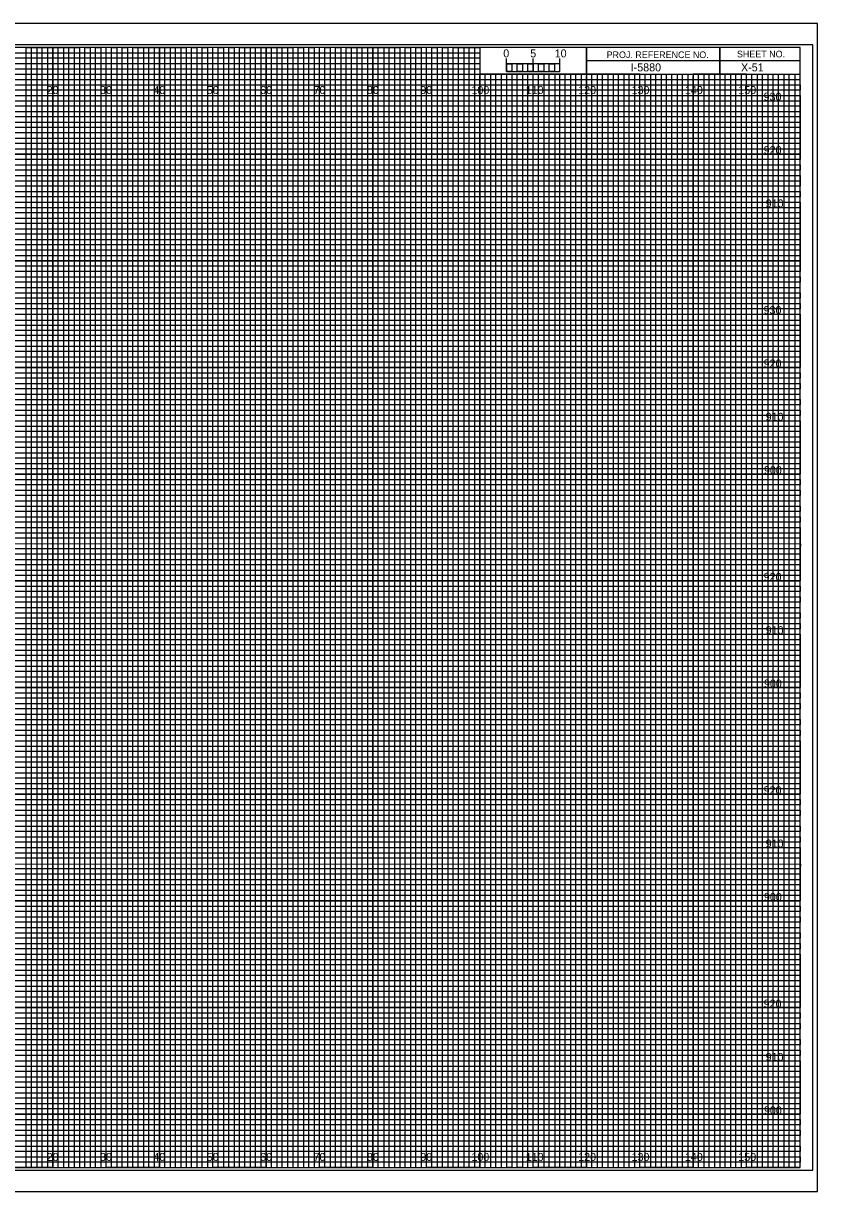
# Model space of a CAD drawing. Extents: x -13 to 323, y 876 to 1094.
# Drawn here: x 174.5 to 323.3, y 875.5 to 1094.5 of the extents above; entities that cross this region are included whole.
import ezdxf

# ---------------------------------------------------------------- set-up
doc = ezdxf.new("R2010")
doc.units = 0
for name, color, linetype in [('Prop XS Bar Scale Labels', 7, 'Continuous'), ('Prop XS Elevation Labels', 7, 'Continuous'), ('Prop XS Offset Labels', 7, 'Continuous'), ('Prop XS Project Number', 7, 'Continuous'), ('Prop XS Sheet Number', 7, 'Continuous'), ('Sheet Cross Section CELL', 7, 'Continuous'), ('Sheet Cross Section Grid Major CELL', 7, 'Continuous'), ('Sheet Cross Section Grid Middle CELL', 7, 'Continuous'), ('Sheet Cross Section Grid Minor 1 CELL', 7, 'Continuous'), ('Sheet Cross Section Grid Minor 2 CELL', 7, 'Continuous'), ('Sheet Cross Section Scale CELL', 7, 'Continuous'), ('Sheet Cutting Line CELL', 7, 'Continuous'), ('Sheet DOT Grid CELL', 7, 'Continuous'), ('Sheet Plot Border Inside CELL', 7, 'Continuous'), ('Sheet Plot Border Outside CELL', 7, 'Continuous')]:
    doc.layers.add(name, color=color, linetype=linetype)

msp = doc.modelspace()

# ---------------------------------------------------------------- linework, layer by layer
at = {"layer": 'Sheet Cross Section CELL'}
for p, q in [((305, 1090), (305, 1085)), ((305, 1085), (305, 1090)), ((280, 1087.5), (280, 1085)), ((320, 1087.49), (280, 1087.49)), ((280, 1085), (320, 1085))]:
    msp.add_line(p, q, dxfattribs=at)
for points in [[(320, 1090), (0, 1090), (0, 880), (320, 880)], [(280, 1090), (260, 1090), (260, 1085.03), (280, 1085.03)], [(320, 1090), (280, 1090), (280, 1085), (320, 1085)]]:
    msp.add_lwpolyline(points, close=True, dxfattribs=at)
at = {"layer": 'Sheet Cross Section Grid Major CELL'}
for p, q in [((190, 1090), (180, 1090)), ((180, 1090), (180, 880)), ((190, 880), (190, 1090)), ((210, 1090), (200, 1090)), ((200, 1090), (200, 880)), ((210, 880), (210, 1090)), ((230, 1090), (220, 1090)), ((220, 1090), (220, 880)), ((230, 880), (230, 1090)), ((250, 1090), (240, 1090)), ((240, 1090), (240, 880)), ((250, 880), (250, 1090)), ((260, 1090), (260, 880)), ((270, 880), (270, 1085)), ((290, 1085), (280, 1085)), ((280, 1085), (280, 880)), ((290, 880), (290, 1085)), ((310, 1085), (300, 1085)), ((300, 1085), (300, 880)), ((310, 880), (310, 1085)), ((180, 880), (170, 880)), ((200, 880), (190, 880)), ((220, 880), (210, 880)), ((240, 880), (230, 880)), ((260, 880), (250, 880)), ((280, 880), (270, 880)), ((300, 880), (290, 880)), ((320, 880), (310, 880)), ((320, 880), (320, 880))]:
    msp.add_line(p, q, dxfattribs=at)
for points in [[(0, 1080), (320, 1080), (320, 1070), (0, 1070)], [(0, 1060), (320, 1060), (320, 1050), (0, 1050)], [(0, 1040), (320, 1040), (320, 1030), (0, 1030)], [(0, 1020), (320, 1020), (320, 1010), (0, 1010)], [(0, 1000), (320, 1000), (320, 990), (0, 990)], [(0, 980), (320, 980), (320, 970), (0, 970)], [(0, 960), (320, 960), (320, 950), (0, 950)], [(0, 940), (320, 940), (320, 930), (0, 930)], [(0, 920), (320, 920), (320, 910), (0, 910)], [(0, 900), (320, 900), (320, 890), (0, 890)]]:
    msp.add_lwpolyline(points, dxfattribs=at)
at = {"layer": 'Sheet Cross Section Grid Middle CELL'}
for points in [[(165, 880), (175, 880), (175, 1090), (185, 1090), (185, 880), (195, 880), (195, 1090), (205, 1090), (205, 880), (215, 880), (215, 1090), (225, 1090), (225, 880), (235, 880), (235, 1090), (245, 1090), (245, 880), (255, 880), (255, 1090), (259.93, 1090), (260, 1090), (260, 1085), (264.99, 1085), (264.99, 880), (275, 880), (275, 1085), (285, 1085), (285, 880), (295, 880), (295, 1085), (305, 1085), (305, 880), (315, 880), (315, 1085)], [(0, 1085), (275, 1085)], [(0, 1065), (320, 1065), (320, 1075), (0, 1075)], [(0, 1045), (320, 1045), (320, 1055), (0, 1055)], [(0, 1025), (320, 1025), (320, 1035), (0, 1035)], [(0, 1005), (320, 1005), (320, 1015), (0, 1015)], [(0, 985), (320, 985), (320, 995), (0, 995)], [(0, 965), (320, 965), (320, 975), (0, 975)], [(0, 945), (320, 945), (320, 955), (0, 955)], [(0, 925), (320, 925), (320, 935), (0, 935)], [(0, 905), (320, 905), (320, 915), (0, 915)], [(0, 885), (320, 885), (320, 895), (0, 895)]]:
    msp.add_lwpolyline(points, dxfattribs=at)
at = {"layer": 'Sheet Cross Section Grid Minor 1 CELL'}
for p, q in [((0, 1089), (260, 1089)), ((260, 1089), (260, 1087.98)), ((260, 1087.98), (0, 1087.98)), ((0, 1087), (260, 1087)), ((260, 1087), (260, 1085.89)), ((260, 1085.89), (0, 1085.89)), ((0, 1084), (320, 1084))]:
    msp.add_line(p, q, dxfattribs=at)
for points in [[(0, 1083), (270, 1083), (320, 1083), (320, 1082), (0, 1082)], [(0, 1081), (320, 1081), (320, 1079), (0, 1079)], [(0, 1078), (320, 1078), (320, 1077), (0, 1076.98)], [(0, 1076), (320, 1076), (320, 1074), (0, 1074)], [(0, 1073), (320, 1073), (320, 1072), (0, 1072)], [(0, 1071), (320, 1071), (320, 1069), (0, 1069)], [(0, 1068), (320, 1068), (320, 1067), (0, 1067)], [(0, 1066), (320, 1066), (320, 1064), (0, 1064)], [(0, 1063), (320, 1063), (320, 1062), (0, 1062)], [(0, 1061), (320, 1061), (320, 1059), (0, 1059)], [(0, 1058), (320, 1058), (320, 1057), (0, 1057)], [(0, 1056), (320, 1056), (320, 1053.95), (320, 1053), (320, 1052), (0, 1052)], [(0, 1054), (320, 1054), (320, 1053), (0, 1053)], [(0, 1051), (320, 1051), (320, 1049), (0, 1049.03)], [(0, 1049.03), (320, 1049), (320, 1048), (0, 1048)], [(0, 1047), (320, 1047), (320, 1046), (0, 1046)], [(0, 1044), (320, 1044), (320, 1043), (0, 1043)], [(0, 1042), (320, 1042), (320, 1041), (0, 1041)], [(-0.07, 1038.89), (320, 1038.89), (320, 1037.88), (-0.07, 1037.88)], [(0, 1037), (320, 1037), (320, 1036), (0, 1036)], [(0, 1034), (320, 1034), (320, 1033), (0, 1033)], [(0, 1032), (320, 1032), (320, 1031), (0, 1031)], [(0, 1029), (320, 1029), (320, 1028), (0, 1028)], [(0, 1027), (320, 1027), (320, 1026), (0, 1026)], [(0, 1024), (320, 1024), (320, 1023), (0, 1023)], [(0, 1022), (320, 1022), (320, 1021), (0, 1021)], [(0, 1019), (320, 1019), (319.99, 1017.98), (0, 1018)], [(0, 1017), (320, 1017), (320, 1016), (0, 1016)], [(0, 1014), (320, 1014), (320, 1013), (0, 1013)], [(0, 1012), (320, 1012), (320, 1011), (0, 1011)], [(0, 1009), (320, 1009), (320, 1008), (0, 1008)], [(0, 1007), (320, 1007), (320, 1006), (0, 1006)], [(0, 1004), (320, 1004), (320, 1003), (0, 1003)], [(0, 1002), (320, 1002), (320, 1001), (0, 1001)], [(0, 999), (320, 999), (320, 998), (0, 998)], [(0, 996.99), (320.07, 996.91), (320, 996), (0, 996)], [(0, 994), (320, 994), (320, 993), (0, 993)], [(0, 992), (320, 992), (320, 991), (0, 991)], [(0, 989), (320, 989), (320, 988), (0, 988)], [(0, 987), (320, 987), (320, 986), (0, 986)], [(0, 984), (320, 984), (320, 983), (0, 983)], [(0, 982), (320, 982), (320, 981), (0, 981)], [(0, 979), (320, 979), (320, 978), (0, 978)], [(0, 977), (320, 977), (320, 976), (0, 976)], [(0, 974), (320, 974), (320, 973), (0, 973)], [(0, 972), (320, 972), (320, 971), (0, 971)], [(0, 969), (320, 969), (320, 968), (0, 968)], [(0, 967), (320, 967), (320, 966), (0, 966)], [(0, 964), (320, 964), (320, 963), (0, 963)], [(0, 962), (320, 962), (320, 961), (0, 961)], [(0, 959), (320, 959), (319.99, 957.98), (0, 958)], [(0, 957), (320, 957), (320, 956), (0, 956)], [(0, 954), (320, 954), (320, 953), (0, 953)], [(0, 952), (320, 952), (320, 951), (0, 951)], [(0, 949), (320, 949), (320, 948), (0, 948)], [(0, 947), (320, 947), (320, 946), (0, 946)], [(0, 944), (320, 944), (320, 943), (0, 943)], [(0, 942), (320, 942), (320, 941), (0, 941)], [(0, 939), (320, 939), (320, 938), (0, 938)], [(0, 936.99), (320.07, 936.91), (320, 936), (0, 936)], [(0, 934), (320, 934), (320, 933), (0, 933)], [(0, 932), (320, 932), (320, 931), (0, 931)], [(0, 929), (320, 929), (320, 928), (0, 928)], [(0, 927), (320, 927), (320, 926), (0, 926)], [(0, 924), (320, 924), (320, 923), (0, 923)], [(0, 922), (320, 922), (320, 921), (0, 921)], [(0, 919), (320, 919), (320, 918), (0, 918)], [(0, 917), (320, 917), (320, 916), (0, 916)], [(0, 914), (320, 914), (320, 913), (0, 913)], [(0, 912), (320, 912), (320, 911), (0, 911)], [(0, 909), (320, 909), (320, 908), (0, 908)], [(0, 907), (320, 907), (320, 906), (0, 906)], [(0, 904), (320, 904), (320, 903), (0, 903)], [(0, 902), (320, 902), (320, 901), (0, 901)], [(0, 899), (320, 899), (320, 898), (0, 898)], [(0, 897), (320, 897), (320, 896), (0, 896)], [(0, 894), (320, 894), (320, 893), (0, 893)], [(0, 892), (320, 892), (320, 891), (0, 891)], [(0, 889), (320, 889), (320, 888), (0, 888)], [(0, 887), (320, 887), (320, 886), (0, 886)], [(0, 884), (320, 884), (320, 883), (0, 883)], [(0, 882), (320, 882), (320, 881), (0, 881)]]:
    msp.add_lwpolyline(points, dxfattribs=at)
at = {"layer": 'Sheet Cross Section Grid Minor 2 CELL'}
for p, q in [((267, 1085), (266.01, 1085)), ((266.01, 1085), (266.01, 880)), ((267, 880), (267, 1085)), ((269, 1085), (268, 1085)), ((268, 1085), (268, 880)), ((269, 880), (269, 1085)), ((266.01, 880), (265, 880)), ((268, 880), (267, 880))]:
    msp.add_line(p, q, dxfattribs=at)
for points in [[(175, 880), (176, 880), (176, 1090), (177, 1090), (177, 880)], [(177, 880), (178, 880), (178, 1090), (179, 1090), (179, 880)], [(180, 880), (181, 880), (181, 1090), (182, 1090), (182, 880)], [(182, 880), (183, 880), (183, 1090), (184, 1090), (184, 880)], [(185, 880), (186, 880), (186, 1090), (187, 1090), (187, 880)], [(187, 880), (188, 880), (188, 1090), (189, 1090), (189, 880)], [(190, 880), (191, 880), (191, 1090), (192, 1090), (192, 880)], [(192, 880), (193, 880), (193, 1090), (194, 1090), (194, 880)], [(195, 880), (196, 880), (196, 1090), (197, 1090), (197, 880)], [(197, 880), (198, 880), (198, 1090), (199, 1090), (199, 880)], [(200, 880), (201, 880), (201, 1090), (202, 1090), (202, 880)], [(202, 880), (203, 880), (203, 1090), (204, 1090), (204, 880)], [(205, 880), (206, 880), (206, 1090), (207, 1090), (207, 880)], [(207, 880), (208, 880), (208, 1090), (209, 1090), (209, 880)], [(210, 880), (211, 880), (211, 1090), (212, 1090), (212, 880)], [(212, 880), (213, 880), (213, 1090), (214, 1090), (214, 880)], [(215, 880), (216, 880), (216, 1090), (217, 1090), (217, 880)], [(217, 880), (218, 880), (218, 1090), (219, 1090), (219, 880)], [(220, 880), (221, 880), (221, 1090), (222, 1090), (222, 880)], [(222, 880), (223, 880), (223, 1090), (224, 1090), (224, 880)], [(225, 880), (226, 880), (226, 1090), (227, 1090), (227, 880)], [(227, 880), (228, 880), (228, 1090), (229, 1090), (229, 880)], [(230, 880), (231, 880), (231, 1090), (232, 1090), (232, 880)], [(232, 880), (233, 880), (233, 1090), (234, 1090), (234, 880)], [(235, 880), (236, 880), (236, 1090), (237, 1090), (237, 880)], [(237, 880), (238, 880), (238, 1090), (239, 1090), (239, 880)], [(240, 880), (241, 880), (241, 1090), (242, 1090), (242, 880)], [(242, 880), (243, 880), (243, 1090), (244, 1090), (244, 880)], [(245, 880), (246, 880), (246, 1090), (247, 1090), (247, 880)], [(247, 880), (248, 880), (248, 1090), (249, 1090), (249, 880)], [(250, 880), (251, 880), (251, 1090), (252, 1090), (252, 880)], [(252, 880), (253, 880), (253, 1090), (254, 1090), (254, 880)], [(255, 880), (256, 880), (256, 1090), (257, 1090), (257, 880)], [(257, 880), (258, 880), (258, 1090), (259, 1090), (259, 880)], [(260, 880), (261, 880), (261, 1085), (262.02, 1085), (262.02, 880)], [(262, 880), (263, 880), (263, 1085), (263.99, 1085), (263.99, 880)], [(270, 880), (270.98, 880), (270.98, 1085), (272, 1085), (272, 880)], [(272, 880), (273, 880), (273, 1085), (274.05, 1085), (274.05, 880)], [(275, 880), (276, 880), (276, 1085), (277, 1085), (277, 880)], [(277, 880), (278, 880), (278, 1085), (279, 1085), (279, 880)], [(280, 880), (281, 880), (281, 1085), (282, 1085), (282, 880)], [(282, 880), (283, 880), (283, 1085), (284, 1085), (284, 880)], [(285, 880), (286, 880), (286, 1085), (287, 1085), (287, 880)], [(287, 880), (288, 880), (288, 1085), (289, 1085), (289, 880)], [(290, 880), (291, 880), (291, 1085), (292, 1085), (292, 880)], [(292, 880), (293, 880), (293, 1085), (294, 1085), (294, 880)], [(295, 880), (296, 880), (296, 1085), (297, 1085), (297, 880)], [(297, 880), (298, 880), (298, 1085), (299, 1085), (299, 880)], [(300, 880), (301, 880), (301, 1085), (302, 1085), (302, 880)], [(302, 880), (303, 880), (303, 1085), (304, 1085), (304, 880)], [(305, 880), (306, 880), (306, 1085), (307, 1085), (307, 880)], [(307, 880), (308, 880), (308, 1085), (309, 1085), (309, 880)], [(310, 880), (311, 880), (311, 1085), (312, 1085), (312, 880)], [(312, 880), (313, 880), (313, 1085), (314, 1085), (314, 880)], [(315, 880), (316, 880), (316, 1085), (317, 1085), (317, 880)], [(317, 880), (318, 880), (318, 1085), (319, 1085), (319, 880)]]:
    msp.add_lwpolyline(points, dxfattribs=at)
at = {"layer": 'Sheet Cross Section Scale CELL'}
for p, q in [((265, 1085.49), (265, 1087.9)), ((265, 1086.9), (265, 1087.9)), ((270, 1085.49), (270, 1087.9)), ((275, 1085.49), (275, 1087.9)), ((275, 1086.9), (275, 1087.9))]:
    msp.add_line(p, q, dxfattribs=at)
for points in [[(275, 1086.9), (265, 1086.9), (265, 1085.49), (275, 1085.49)], [(265, 1086.9), (266, 1086.9), (266, 1085.49), (265, 1085.49)], [(267, 1086.9), (268, 1086.9), (268, 1085.49), (267, 1085.49)], [(269, 1086.9), (270, 1086.9), (270, 1085.49), (269, 1085.49)], [(271, 1086.9), (272, 1086.9), (272, 1085.49), (271, 1085.49)], [(273, 1086.9), (274, 1086.9), (274, 1085.49), (273, 1085.49)]]:
    msp.add_lwpolyline(points, close=True, dxfattribs=at)
at = {"layer": 'Sheet Cutting Line CELL'}
for p, q in [((323.3, 1094.5), (-13.4, 1094.5)), ((-13.4, 875.5), (323.3, 875.5))]:
    msp.add_line(p, q, dxfattribs=at)
at = {"layer": 'Sheet DOT Grid CELL'}
for p, q in [((180, 880), (180, 1090)), ((190, 880), (190, 1090)), ((200, 880), (200, 1090)), ((210, 880), (210, 1090)), ((220, 880), (220, 1090)), ((230, 880), (230, 1090)), ((240, 880), (240, 1090)), ((250, 880), (250, 1090)), ((260, 880), (260, 1084.69)), ((270, 880), (270, 1084.69)), ((280, 880), (280, 1084.69)), ((290, 880), (290, 1084.69)), ((300, 880), (300, 1084.69)), ((310, 880), (310, 1084.69)), ((0, 1080), (320, 1080)), ((0, 1070), (320, 1070)), ((0, 1060), (320, 1060)), ((0, 1050), (320, 1050)), ((0, 1040), (320, 1040)), ((0, 1030), (320, 1030)), ((0, 1020), (320, 1020)), ((0, 1010), (320, 1010)), ((0, 1000), (320, 1000)), ((0, 990), (320, 990)), ((0, 980), (320, 980)), ((0, 970), (320, 970)), ((0, 960), (320, 960)), ((0, 950), (320, 950)), ((0, 940), (320, 940)), ((0, 930), (320, 930)), ((0, 920), (320, 920)), ((0, 910), (320, 910)), ((0, 900), (320, 900)), ((0, 890), (320, 890))]:
    msp.add_line(p, q, dxfattribs=at)
at = {"layer": 'Sheet Plot Border Inside CELL'}
msp.add_lwpolyline([(-10.8, 879.5), (322.4, 879.5), (322.4, 1090.5), (-10.8, 1090.5)], close=True, dxfattribs=at)
at = {"layer": 'Sheet Plot Border Outside CELL'}
msp.add_lwpolyline([(-13.4, 875.5), (323.3, 875.5), (323.3, 1094.5), (-13.4, 1094.5)], close=True, dxfattribs=at)

# ---------------------------------------------------------------- texts
at = {"layer": 'Prop XS Bar Scale Labels'}
for s, p in [('5', (269.47, 1088.12)), ('10', (274.04, 1088.12))]:
    msp.add_text(s, height=1.5, dxfattribs=at).set_placement(p)
at = {"layer": 'Prop XS Elevation Labels'}
for s, p in [('930', (313.18, 1080)), ('920', (313.19, 1070)), ('910', (313.57, 1060)), ('930', (313.18, 1040)), ('920', (313.19, 1030)), ('910', (313.57, 1020)), ('900', (313.24, 1010)), ('920', (313.19, 990)), ('910', (313.57, 980)), ('900', (313.24, 970)), ('920', (313.19, 950)), ('910', (313.57, 940)), ('900', (313.24, 930)), ('920', (313.19, 910)), ('910', (313.57, 900)), ('900', (313.24, 890))]:
    msp.add_text(s, height=1.5, dxfattribs=at).set_placement(p)
at = {"layer": 'Prop XS Offset Labels'}
for s, p in [('20', (178.86, 1081.25)), ('30', (188.86, 1081.25)), ('40', (198.86, 1081.25)), ('50', (208.86, 1081.25)), ('60', (218.86, 1081.25)), ('70', (228.86, 1081.25)), ('80', (238.86, 1081.25)), ('90', (248.86, 1081.25)), ('100', (258.44, 1081.25)), ('110', (268.62, 1081.25)), ('120', (278.44, 1081.25)), ('130', (288.44, 1081.25)), ('140', (298.44, 1081.25)), ('150', (308.44, 1081.25)), ('20', (178.86, 881.25)), ('30', (188.86, 881.25)), ('40', (198.86, 881.25)), ('50', (208.86, 881.25)), ('60', (218.86, 881.25)), ('70', (228.86, 881.25)), ('80', (238.86, 881.25)), ('90', (248.86, 881.25)), ('100', (258.44, 881.25)), ('110', (268.62, 881.25)), ('120', (278.44, 881.25)), ('130', (288.44, 881.25)), ('140', (298.44, 881.25)), ('150', (308.44, 881.25))]:
    msp.add_text(s, height=1.5, dxfattribs=at).set_placement(p)
at = {"layer": 'Prop XS Project Number'}
msp.add_text('I-5880', height=1.5, dxfattribs=at).set_placement((288.28, 1085.5))
at = {"layer": 'Prop XS Sheet Number'}
msp.add_text('X-51', height=1.5, dxfattribs=at).set_placement((308.95, 1085.5))
at = {"layer": 'Sheet Cross Section CELL'}
for s, p in [('PROJ. REFERENCE NO.', (283.77, 1087.99)), ('SHEET NO.', (308.19, 1088.12))]:
    msp.add_text(s, height=1.25, dxfattribs=at).set_placement(p)
at = {"layer": 'Sheet Cross Section Scale CELL'}
msp.add_text('0', height=1.5, dxfattribs=at).set_placement((264.41, 1088.12))

doc.saveas('drawing.dxf')
